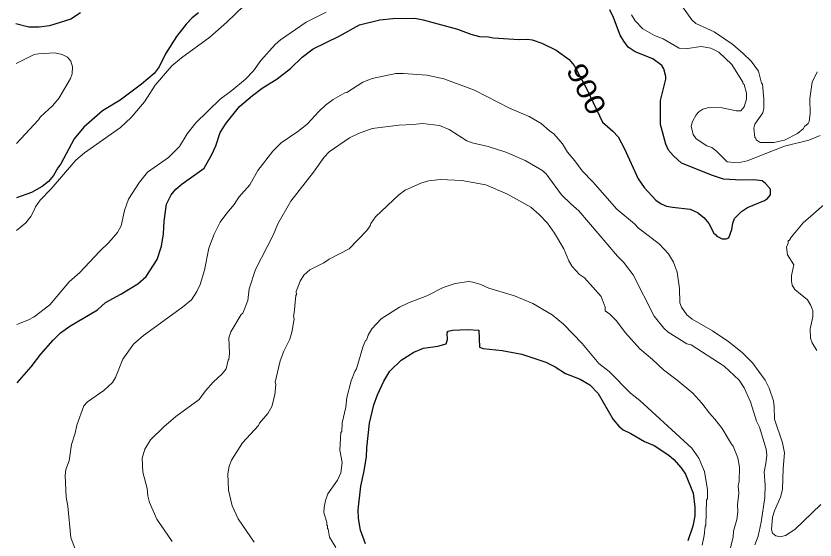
# Model space of a CAD drawing. Extents: x 447.8 to 473.9, y 7733.1 to 7760.8.
# Drawn here: x 447.821 to 451.054, y 7744.508 to 7746.626 of the extents above; entities that cross this region are included whole.
import ezdxf
from ezdxf.enums import TextEntityAlignment as Align

# ---------------------------------------------------------------- set-up
doc = ezdxf.new("R2010")
doc.units = 0
doc.header["$LTSCALE"] = 0.032
doc.layers.add('1', color=7, linetype='Continuous', lineweight=25)
doc.layers.add('2', color=7, linetype='Continuous', lineweight=13)
doc.layers.add('61', color=7, linetype='Continuous')

msp = doc.modelspace()

# ---------------------------------------------------------------- linework, layer by layer
at = {"layer": '1'}
for points in [[(448.0811, 7746.6387), (448.0428, 7746.6138), (447.9561, 7746.5864), (447.9149, 7746.5808), (447.8721, 7746.5808), (447.8206, 7746.595)], [(448.5598, 7746.6398), (448.5331, 7746.6186), (448.5089, 7746.5935), (448.4697, 7746.5441), (448.4256, 7746.4736), (448.3995, 7746.4204), (448.3802, 7746.3937), (448.329, 7746.3513), (448.2422, 7746.2859), (448.1713, 7746.2432), (448.0957, 7746.1772), (448.0567, 7746.1302), (448.0024, 7746.0288), (447.9897, 7746.0127), (447.9721, 7745.9813), (447.9523, 7745.9577), (447.9263, 7745.9366), (447.8837, 7745.9131), (447.8228, 7745.8908)], [(450.2661, 7746.5484), (450.2386, 7746.6208), (450.2236, 7746.651)], [(447.8251, 7745.1427), (447.8826, 7745.2082), (447.921, 7745.2595), (447.9709, 7745.3158), (448.0009, 7745.3451), (448.0388, 7745.3727), (448.1504, 7745.4386), (448.183, 7745.4681), (448.245, 7745.5014), (448.3138, 7745.5436), (448.3475, 7745.5737), (448.3922, 7745.6422), (448.4094, 7745.6958), (448.4182, 7745.7452), (448.4206, 7745.7968), (448.43, 7745.8662), (448.4489, 7745.9037), (448.4677, 7745.9256), (448.4926, 7745.9473), (448.5824, 7746.0117), (448.6129, 7746.0658), (448.6289, 7746.1011), (448.6468, 7746.1558), (448.6705, 7746.1925), (448.7252, 7746.2609), (448.7775, 7746.3054), (448.8168, 7746.3342), (448.8772, 7746.3721), (448.931, 7746.4138), (448.9791, 7746.4602), (449.0237, 7746.4935), (449.1279, 7746.5447), (449.2103, 7746.5908), (449.2932, 7746.6113), (449.3454, 7746.616), (449.4342, 7746.6176), (449.4688, 7746.6113), (449.6079, 7746.5734), (449.6617, 7746.5523), (449.697, 7746.5441), (449.7322, 7746.5424), (449.751, 7746.5383), (449.8563, 7746.5311), (449.8923, 7746.5326), (449.9097, 7746.5295), (449.9489, 7746.516), (450.0063, 7746.4882), (450.059, 7746.4501), (450.0796, 7746.4265), (450.1315, 7746.3274), (450.1936, 7746.1972), (450.2359, 7746.161), (450.2572, 7746.1379), (450.2834, 7746.0889), (450.3387, 7745.9686), (450.3633, 7745.9331), (450.4104, 7745.8823), (450.431, 7745.8674), (450.4531, 7745.8579), (450.4772, 7745.853), (450.5493, 7745.8457), (450.579, 7745.8314), (450.6041, 7745.8112), (450.625, 7745.7872), (450.6457, 7745.7459), (450.6506, 7745.7446), (450.6574, 7745.7357), (450.6787, 7745.7258), (450.6947, 7745.7255), (450.7052, 7745.7298), (450.7179, 7745.7628), (450.7212, 7745.7885), (450.7285, 7745.808), (450.7562, 7745.8358), (450.7814, 7745.8525), (450.8501, 7745.8805), (450.8624, 7745.8884), (450.8738, 7745.9028), (450.874, 7745.9261), (450.8542, 7745.9491), (450.8401, 7745.9593), (450.8065, 7745.9635), (450.7572, 7745.962), (450.6842, 7745.9672), (450.6387, 7745.9816), (450.514, 7746.0315), (450.4809, 7746.0612), (450.4613, 7746.0841), (450.4509, 7746.1077), (450.4294, 7746.1872), (450.4294, 7746.2854), (450.4502, 7746.3715), (450.4502, 7746.382), (450.4427, 7746.4123), (450.4347, 7746.4262)], [(450.4347, 7746.4262), (450.3973, 7746.4533), (450.3268, 7746.4822), (450.2985, 7746.501), (450.2798, 7746.5243), (450.2661, 7746.5484)], [(449.2347, 7744.4926), (449.2147, 7744.5481), (449.207, 7744.594), (449.2048, 7744.6291), (449.2162, 7744.7253), (449.2286, 7744.7804), (449.2386, 7744.8439), (449.2399, 7744.8802), (449.2508, 7744.9802), (449.2686, 7745.0542), (449.2829, 7745.0945), (449.3089, 7745.1493), (449.3334, 7745.1899), (449.3795, 7745.2351), (449.4303, 7745.2676), (449.4695, 7745.283), (449.5272, 7745.2911), (449.5618, 7745.3009), (449.5662, 7745.3181), (449.5656, 7745.3453), (449.5695, 7745.3526), (449.5877, 7745.3567), (449.6469, 7745.3591), (449.6931, 7745.3559), (449.6968, 7745.288), (449.7116, 7745.2821), (449.7885, 7745.2741), (449.868, 7745.259), (449.9648, 7745.2267), (450.003, 7745.2076), (450.0443, 7745.1813), (450.1043, 7745.1578), (450.1427, 7745.1353), (450.1767, 7745.1005), (450.2377, 7744.9951), (450.2602, 7744.9679), (450.2778, 7744.9532), (450.3084, 7744.9387), (450.3646, 7744.9058), (450.4034, 7744.8896), (450.4622, 7744.8512), (450.4828, 7744.8327), (450.5122, 7744.7995), (450.5306, 7744.7737), (450.5615, 7744.6974), (450.5673, 7744.6401), (450.5674, 7744.6048), (450.5602, 7744.5631), (450.5391, 7744.5043)]]:
    msp.add_lwpolyline(points, dxfattribs=at)
at = {"layer": '2'}
for points in [[(447.8232, 7745.7592), (447.8603, 7745.7904), (447.8806, 7745.8163), (447.8948, 7745.8417), (447.8992, 7745.8552), (447.9186, 7745.8823), (447.9627, 7745.9272), (448.0633, 7746.043), (448.0979, 7746.0725), (448.2441, 7746.1758), (448.2874, 7746.2166), (448.3405, 7746.2787), (448.3844, 7746.3473), (448.4512, 7746.4253), (448.4903, 7746.4578), (448.6056, 7746.5412), (448.6742, 7746.6019), (448.7435, 7746.6694)], [(450.508, 7746.677), (450.5558, 7746.6115), (450.572, 7746.5964), (450.646, 7746.5619), (450.721, 7746.5112), (450.7637, 7746.4749), (450.7953, 7746.4433), (450.8254, 7746.4028), (450.8375, 7746.3542), (450.8414, 7746.3504), (450.847, 7746.2896), (450.847, 7746.254), (450.8427, 7746.2354), (450.8112, 7746.1892), (450.807, 7746.1724), (450.8109, 7746.1355), (450.8142, 7746.1331), (450.8161, 7746.1256), (450.8322, 7746.1153), (450.887, 7746.1143), (450.9303, 7746.1241), (450.9832, 7746.1513), (451.0057, 7746.1696), (451.0122, 7746.1799), (451.0258, 7746.1911), (451.0306, 7746.1996), (451.0338, 7746.2313), (451.0331, 7746.2924), (451.0419, 7746.3595), (451.0627, 7746.4002)], [(449.0758, 7746.6417), (448.9949, 7746.6017), (448.8904, 7746.5294), (448.8693, 7746.5115), (448.8108, 7746.4467), (448.7812, 7746.4041), (448.7496, 7746.371), (448.6946, 7746.3248), (448.6467, 7746.2897), (448.5487, 7746.1942), (448.513, 7746.1498), (448.4829, 7746.0988), (448.4377, 7746.0545), (448.3526, 7745.9956), (448.32, 7745.9549), (448.2764, 7745.8857), (448.26, 7745.8405), (448.2459, 7745.7775), (448.2317, 7745.7506), (448.1968, 7745.7108), (448.1583, 7745.6739), (448.0786, 7745.5889), (448.0365, 7745.552), (447.9571, 7745.4583), (447.8945, 7745.4103), (447.8688, 7745.3967), (447.8244, 7745.3794)], [(451.0748, 7746.1435), (451.0294, 7746.1242), (450.9301, 7746.0999), (450.7801, 7746.0403), (450.7426, 7746.0333), (450.6983, 7746.0369), (450.6559, 7746.0804), (450.6361, 7746.0941), (450.6164, 7746.1009), (450.5735, 7746.1303), (450.5606, 7746.1471), (450.5523, 7746.1804), (450.5578, 7746.1994), (450.5726, 7746.2263), (450.5842, 7746.239), (450.6006, 7746.2502), (450.6245, 7746.2569), (450.6779, 7746.2546), (450.7348, 7746.2425), (450.7538, 7746.2424), (450.7671, 7746.2591), (450.7765, 7746.2899), (450.7772, 7746.3142), (450.7678, 7746.3499), (450.7632, 7746.3524), (450.7618, 7746.3583), (450.7169, 7746.4302), (450.6647, 7746.4798), (450.6323, 7746.4958), (450.5932, 7746.5028), (450.5378, 7746.495), (450.5043, 7746.4966), (450.4393, 7746.5346), (450.4043, 7746.5471), (450.357, 7746.5739), (450.3267, 7746.6063), (450.3118, 7746.6317)], [(447.8211, 7746.4344), (447.8939, 7746.4703), (447.9121, 7746.4741), (447.9774, 7746.4774), (448.0076, 7746.4713), (448.0289, 7746.4594), (448.042, 7746.4435), (448.0487, 7746.421), (448.0479, 7746.3931), (448.0406, 7746.3737), (447.9948, 7746.2956), (447.9693, 7746.2649), (447.9201, 7746.2181), (447.9122, 7746.2062), (447.8221, 7746.1105)], [(448.0603, 7744.47), (448.0426, 7744.518), (448.0311, 7744.6441), (448.0231, 7744.6811), (448.0198, 7744.7682), (448.023, 7744.7925), (448.0359, 7744.8274), (448.0458, 7744.8936), (448.0604, 7744.9399), (448.0669, 7744.9716), (448.0958, 7745.0508), (448.1094, 7745.0661), (448.1755, 7745.1117), (448.2111, 7745.1442), (448.223, 7745.1645), (448.2526, 7745.2392), (448.2968, 7745.3001), (448.3372, 7745.334), (448.4949, 7745.4485), (448.5303, 7745.4793), (448.5526, 7745.5127), (448.5662, 7745.5413), (448.5838, 7745.5985), (448.6005, 7745.6872), (448.623, 7745.7448), (448.6475, 7745.7932), (448.6734, 7745.829), (448.7041, 7745.8641), (448.7223, 7745.8933), (448.7668, 7745.9443), (448.7999, 7746.0016), (448.8595, 7746.0802), (448.8934, 7746.114), (448.9607, 7746.1589), (448.9995, 7746.1897), (449.0457, 7746.2407), (449.0725, 7746.2653), (449.1043, 7746.2888), (449.1512, 7746.3152), (449.1598, 7746.3173), (449.2243, 7746.3592), (449.2622, 7746.3738), (449.3578, 7746.3946), (449.3884, 7746.3946), (449.4833, 7746.3867), (449.5519, 7746.3727), (449.6766, 7746.3262), (449.8173, 7746.2534), (449.8977, 7746.2204), (449.9465, 7746.1912), (449.9791, 7746.1625), (449.9969, 7746.1506), (450.0317, 7746.1093), (450.0521, 7746.0765), (450.0819, 7746.0414), (450.1113, 7746.0004), (450.1547, 7745.956), (450.2525, 7745.8454), (450.3233, 7745.7865), (450.3399, 7745.7692), (450.4234, 7745.7049), (450.4618, 7745.6642), (450.482, 7745.6305), (450.4968, 7745.5908), (450.5062, 7745.5249), (450.5065, 7745.4666), (450.5132, 7745.4495), (450.5347, 7745.4182), (450.557, 7745.401), (450.6389, 7745.3537), (450.7054, 7745.3087), (450.7604, 7745.264), (450.801, 7745.2238), (450.8527, 7745.1543), (450.8691, 7745.1213), (450.8862, 7745.0709), (450.8894, 7745.0472), (450.8905, 7744.996), (450.9231, 7744.9007), (450.9311, 7744.8604)], [(449.4281, 7746.1872), (449.3701, 7746.1848), (449.262, 7746.171), (449.2067, 7746.1518), (449.1699, 7746.1337), (449.0883, 7746.0767)], [(450.8101, 7744.4876), (450.8237, 7744.5236), (450.8365, 7744.5793), (450.8504, 7744.6796), (450.8527, 7744.7297), (450.8479, 7744.7836), (450.8557, 7744.8165), (450.859, 7744.8513), (450.8558, 7744.875), (450.829, 7744.9636), (450.8172, 7744.9879), (450.7932, 7745.066), (450.7674, 7745.1225), (450.7473, 7745.1541), (450.6865, 7745.2104), (450.5528, 7745.2966), (450.5355, 7745.3007), (450.4604, 7745.3483), (450.4424, 7745.3646), (450.4025, 7745.413), (450.3176, 7745.5797), (450.2797, 7745.6314), (450.2547, 7745.6548), (450.0989, 7745.838), (450.0656, 7745.8664), (450.0286, 7745.9033), (449.966, 7745.9882), (449.949, 7746.0032), (449.8805, 7746.0423), (449.8029, 7746.0756), (449.7317, 7746.0983), (449.6663, 7746.113), (449.6457, 7746.1213), (449.5731, 7746.1673), (449.5348, 7746.1831), (449.4653, 7746.1919), (449.4281, 7746.1872)], [(449.0883, 7746.0767), (449.0683, 7746.0557), (449.0247, 7745.9954), (448.9322, 7745.8772), (448.8804, 7745.7866), (448.8619, 7745.7397), (448.7895, 7745.601), (448.7638, 7745.5226), (448.7587, 7745.4755), (448.738, 7745.4251), (448.7318, 7745.4192), (448.6898, 7745.3499), (448.682, 7745.3251), (448.6851, 7745.2613), (448.6819, 7745.2377), (448.6789, 7745.2342), (448.6707, 7745.1997), (448.6553, 7745.1794), (448.6192, 7745.1456), (448.588, 7745.1104), (448.5623, 7745.0759), (448.4677, 7745.0073), (448.4188, 7744.9653), (448.3653, 7744.9127), (448.3424, 7744.8756), (448.3317, 7744.8385), (448.3342, 7744.7821), (448.3518, 7744.7155), (448.3535, 7744.6868), (448.3614, 7744.6589), (448.3903, 7744.5913), (448.4526, 7744.5015)], [(450.746, 7744.6964), (450.7437, 7744.727), (450.7468, 7744.7452), (450.7484, 7744.8028), (450.742, 7744.8397), (450.7229, 7744.8875), (450.7156, 7744.8952), (450.6778, 7744.9581), (450.6492, 7744.9966), (450.627, 7745.0203), (450.5967, 7745.0612), (450.56, 7745.101), (450.4957, 7745.1541), (450.4404, 7745.1953), (450.3963, 7745.2375), (450.3447, 7745.2811), (450.2876, 7745.3455), (450.2488, 7745.3955), (450.2237, 7745.4214), (450.2051, 7745.4347), (450.2048, 7745.4489), (450.1889, 7745.4922), (450.1209, 7745.5683), (450.1004, 7745.5814), (450.0711, 7745.6139), (450.0574, 7745.6368), (450.0381, 7745.6849), (450.0003, 7745.749), (449.9719, 7745.7886), (449.9378, 7745.8242), (449.9039, 7745.8535), (449.8103, 7745.906), (449.7214, 7745.944), (449.6249, 7745.9619), (449.5381, 7745.9651), (449.4906, 7745.9596), (449.4588, 7745.9508), (449.3957, 7745.922), (449.3695, 7745.904), (449.2749, 7745.815), (449.2561, 7745.7875), (449.2535, 7745.7776), (449.241, 7745.7586), (449.1693, 7745.6855), (449.0876, 7745.6437), (449.0667, 7745.6284), (449.0101, 7745.6001), (448.986, 7745.5784), (448.9701, 7745.5538), (448.9547, 7745.5121), (448.9561, 7745.5006), (448.953, 7745.4964), (448.9465, 7745.4252), (448.9435, 7745.4158), (448.9457, 7745.4011), (448.9368, 7745.3479), (448.9288, 7745.3191), (448.9048, 7745.2709), (448.8903, 7745.2319), (448.8696, 7745.146), (448.872, 7745.137), (448.868, 7745.0953), (448.856, 7745.0468), (448.8403, 7745.019), (448.8063, 7744.98), (448.802, 7744.9709), (448.737, 7744.9012), (448.6934, 7744.8304), (448.6835, 7744.8057), (448.6774, 7744.7747), (448.6812, 7744.7095), (448.6957, 7744.6463), (448.7202, 7744.5935), (448.7849, 7744.4993)], [(451.0621, 7745.2738), (451.042, 7745.3043), (451.0356, 7745.3232), (451.0339, 7745.3619), (451.0449, 7745.4104), (451.0448, 7745.4345), (451.0365, 7745.4562), (451.023, 7745.4789), (450.9725, 7745.5207), (450.962, 7745.5381), (450.9585, 7745.5536), (450.9585, 7745.577), (450.9678, 7745.6199), (450.9428, 7745.6608), (450.9393, 7745.6922), (450.9455, 7745.7081), (450.946, 7745.7185), (450.9498, 7745.719), (450.9588, 7745.7339), (451.0068, 7745.7906), (451.1009, 7745.8724)], [(450.5977, 7744.487), (450.6057, 7744.5252), (450.609, 7744.5636), (450.6122, 7744.5683), (450.6155, 7744.6681), (450.6186, 7744.6755), (450.6186, 7744.7101), (450.6073, 7744.785), (450.5838, 7744.8388), (450.5558, 7744.8793), (450.3458, 7745.0715), (450.3074, 7745.1013), (450.2207, 7745.189), (450.179, 7745.2215), (450.1124, 7745.3019), (450.0368, 7745.3807), (449.9899, 7745.4181), (449.9122, 7745.4646), (449.8385, 7745.4944), (449.7343, 7745.5256), (449.7019, 7745.541), (449.6695, 7745.5507), (449.6529, 7745.5523), (449.5977, 7745.5452), (449.5487, 7745.528), (449.483, 7745.4956), (449.4087, 7745.4668), (449.3727, 7745.4493), (449.2979, 7745.4018), (449.2612, 7745.3613), (449.2452, 7745.3353), (449.2387, 7745.3159), (449.235, 7745.3146), (449.2243, 7745.287), (449.1986, 7745.1999), (449.1918, 7745.189), (449.1775, 7745.1514), (449.1598, 7745.0837), (449.1549, 7745.0449), (449.1409, 7744.9808), (449.1388, 7744.9458), (449.1357, 7744.9427), (449.1317, 7744.8712), (449.1405, 7744.8216), (449.1351, 7744.7792), (449.1212, 7744.75), (449.0828, 7744.6938), (449.0732, 7744.6678), (449.0675, 7744.6406), (449.0668, 7744.6179), (449.0779, 7744.5794), (449.078, 7744.5675), (449.0811, 7744.5653), (449.0812, 7744.5542), (449.0843, 7744.5513), (449.0891, 7744.5193), (449.1144, 7744.478)], [(450.9311, 7744.8604), (450.9248, 7744.7969), (450.9231, 7744.7122), (450.9148, 7744.6804), (450.8897, 7744.6255), (450.8815, 7744.6003)], [(450.7228, 7744.5204), (450.7244, 7744.5436), (450.7379, 7744.5906), (450.7421, 7744.6211), (450.7405, 7744.6492), (450.746, 7744.6964)], [(450.8815, 7744.6003), (450.8784, 7744.55), (450.8826, 7744.5354), (450.8949, 7744.524), (450.915, 7744.5204), (450.9342, 7744.5264), (450.9729, 7744.5506), (451.0774, 7744.6515)], [(450.7068, 7744.4535), (450.7228, 7744.5204)]]:
    msp.add_lwpolyline(points, dxfattribs=at)

# ---------------------------------------------------------------- texts
at = {"layer": '61', "width": 1.2}
msp.add_text('900', height=0.08, rotation=297.237, dxfattribs=at).set_placement((450.0937, 7746.3133), align=Align.CENTER)

doc.saveas('drawing.dxf')
